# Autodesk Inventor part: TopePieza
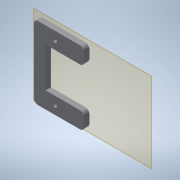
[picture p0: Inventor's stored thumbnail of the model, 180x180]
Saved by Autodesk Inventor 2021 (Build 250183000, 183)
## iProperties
Created: 2021-02
Part Number: TopePieza
Material: Genérico
Document SubType Name: Modeling
Designer: ATOUZA
Density: 1 g/cm^3
Appearance: Valor por defecto
Author: ATOUZA
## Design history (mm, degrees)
node "Plano de trabajo1"
extrude "Extrusión1" new body sketch "Boceto1" distance "d3" = 5; taper "d4" = 0 deg
fillet "Empalme1" dims "d5" = 4
node "Sólido1"
other parameters: "d0" = 1, "d1" = 4, "d2" = 4
